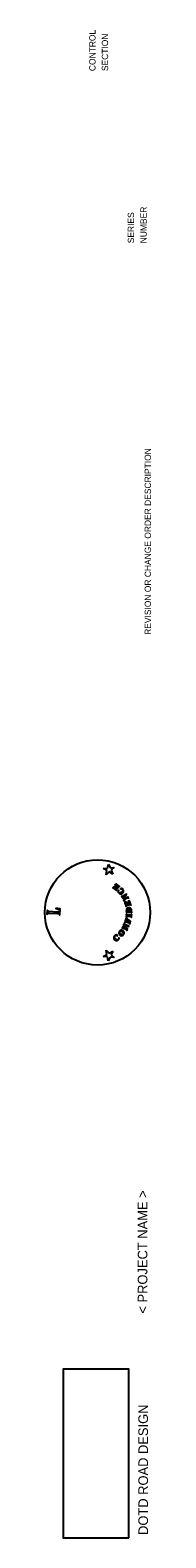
# Model space of a CAD drawing. Extents: x -31.4 to 41.1, y -13.7 to 22.3.
# Drawn here: x 39.92 to 41.13, y 0.56 to 17.76 of the extents above; entities that cross this region are included whole.
import ezdxf

# ---------------------------------------------------------------- set-up
doc = ezdxf.new("R2010")
doc.units = 0
doc.layers.add('Seal', color=7, linetype='Continuous')
doc.layers.add('Sheet Border', color=7, linetype='Continuous')

msp = doc.modelspace()

# ---------------------------------------------------------------- linework, layer by layer
at = {"layer": 'Seal'}
msp.add_lwpolyline([(40.878, 0.558), (40.878, 2.481), (40.128, 2.481), (40.128, 0.558)], close=True, dxfattribs=at)
at = {"layer": 'Sheet Border'}
for p, q in [((40.587, 8.192), (40.635, 8.198)), ((40.629, 8.169), (40.587, 8.192)), ((40.619, 8.122), (40.629, 8.169)), ((40.654, 8.154), (40.619, 8.122)), ((40.635, 8.198), (40.645, 8.244)), ((40.645, 8.244), (40.664, 8.2)), ((40.695, 8.13), (40.654, 8.154)), ((40.664, 8.2), (40.712, 8.206)), ((40.712, 8.206), (40.676, 8.174)), ((40.676, 8.174), (40.695, 8.13)), ((40.629, 7.214), (40.62, 7.261)), ((40.62, 7.261), (40.654, 7.229)), ((40.654, 7.229), (40.696, 7.252)), ((40.696, 7.252), (40.676, 7.209)), ((40.587, 7.191), (40.629, 7.214)), ((40.635, 7.185), (40.587, 7.191)), ((40.644, 7.139), (40.635, 7.185)), ((40.664, 7.183), (40.644, 7.139)), ((40.711, 7.177), (40.664, 7.183)), ((40.676, 7.209), (40.711, 7.177))]:
    msp.add_line(p, q, dxfattribs=at)
for points in [[(40.721, 7.958), (40.715, 7.963), (40.708, 7.969), (40.706, 7.973), (40.706, 7.976), (40.706, 7.98), (40.708, 7.985), (40.707, 7.986), (40.697, 7.974), (40.737, 7.942), (40.737, 7.943), (40.736, 7.945), (40.734, 7.947), (40.733, 7.949), (40.733, 7.951), (40.736, 7.955), (40.761, 7.986), (40.764, 7.99), (40.767, 7.991), (40.771, 7.989), (40.773, 7.987), (40.773, 7.988), (40.733, 8.02), (40.72, 8.007), (40.721, 8.007), (40.727, 8.01), (40.734, 8.011), (40.741, 8.01), (40.747, 8.006), (40.75, 8.004), (40.753, 8.001), (40.753, 7.998), (40.749, 7.993), (40.739, 7.98), (40.736, 7.983), (40.734, 7.985), (40.733, 7.988), (40.733, 7.991), (40.734, 7.995), (40.736, 7.999), (40.735, 8), (40.717, 7.977), (40.718, 7.976), (40.723, 7.98), (40.727, 7.982), (40.731, 7.982), (40.736, 7.979), (40.737, 7.978)], [(40.748, 7.931), (40.749, 7.93), (40.752, 7.931), (40.754, 7.93), (40.756, 7.925), (40.76, 7.919), (40.764, 7.914), (40.77, 7.909), (40.778, 7.906), (40.786, 7.905), (40.795, 7.906), (40.802, 7.909), (40.809, 7.914), (40.814, 7.92), (40.817, 7.927), (40.818, 7.935), (40.817, 7.942), (40.814, 7.95), (40.808, 7.957), (40.803, 7.961), (40.798, 7.964), (40.793, 7.966), (40.786, 7.967), (40.783, 7.963), (40.79, 7.963), (40.795, 7.962), (40.8, 7.96), (40.804, 7.957), (40.808, 7.952), (40.809, 7.947), (40.809, 7.942), (40.806, 7.936), (40.802, 7.929), (40.797, 7.924), (40.79, 7.918), (40.784, 7.915), (40.778, 7.913), (40.773, 7.913), (40.768, 7.915), (40.763, 7.918), (40.76, 7.923), (40.759, 7.93), (40.76, 7.937), (40.764, 7.944), (40.763, 7.945)], [(40.045, 7.74), (40.045, 7.737), (40.06, 7.733), (40.071, 7.73), (40.078, 7.726), (40.083, 7.722), (40.086, 7.718), (40.087, 7.712), (40.086, 7.706), (40.085, 7.699), (40.08, 7.696), (40.065, 7.697), (39.969, 7.702), (39.956, 7.703), (39.951, 7.706), (39.949, 7.711), (39.949, 7.714), (39.946, 7.714), (39.943, 7.674), (39.947, 7.674), (39.947, 7.676), (39.949, 7.681), (39.954, 7.684), (39.969, 7.684), (40.066, 7.679), (40.08, 7.677), (40.085, 7.674), (40.087, 7.669), (40.087, 7.666), (40.09, 7.666), (40.094, 7.734)], [(40.815, 7.843), (40.826, 7.826), (40.827, 7.827), (40.825, 7.83), (40.826, 7.835), (40.827, 7.836), (40.863, 7.858), (40.867, 7.86), (40.87, 7.86), (40.873, 7.858), (40.875, 7.855), (40.876, 7.856), (40.866, 7.872), (40.865, 7.872), (40.866, 7.871), (40.867, 7.868), (40.867, 7.865), (40.866, 7.863), (40.862, 7.86), (40.828, 7.84), (40.851, 7.901), (40.85, 7.902), (40.808, 7.877), (40.803, 7.874), (40.799, 7.875), (40.796, 7.879), (40.794, 7.878), (40.804, 7.861), (40.805, 7.862), (40.804, 7.866), (40.804, 7.869), (40.806, 7.872), (40.81, 7.874), (40.832, 7.888)], [(40.842, 7.781), (40.84, 7.788), (40.838, 7.797), (40.838, 7.801), (40.839, 7.805), (40.842, 7.808), (40.847, 7.811), (40.846, 7.812), (40.831, 7.807), (40.846, 7.759), (40.847, 7.76), (40.846, 7.762), (40.846, 7.764), (40.846, 7.766), (40.848, 7.769), (40.853, 7.77), (40.89, 7.782), (40.896, 7.783), (40.898, 7.782), (40.9, 7.778), (40.901, 7.776), (40.902, 7.776), (40.887, 7.825), (40.869, 7.822), (40.869, 7.821), (40.876, 7.82), (40.883, 7.818), (40.887, 7.813), (40.891, 7.806), (40.892, 7.802), (40.892, 7.798), (40.891, 7.796), (40.885, 7.794), (40.869, 7.789), (40.868, 7.793), (40.868, 7.796), (40.869, 7.799), (40.871, 7.801), (40.874, 7.804), (40.878, 7.806), (40.877, 7.807), (40.849, 7.799), (40.849, 7.797), (40.855, 7.798), (40.86, 7.797), (40.864, 7.794), (40.866, 7.79), (40.866, 7.788)], [(40.911, 7.689), (40.909, 7.715), (40.908, 7.723), (40.907, 7.728), (40.905, 7.733), (40.902, 7.736), (40.899, 7.74), (40.895, 7.742), (40.89, 7.744), (40.885, 7.746), (40.879, 7.746), (40.87, 7.744), (40.863, 7.741), (40.86, 7.738), (40.857, 7.736), (40.855, 7.732), (40.853, 7.729), (40.851, 7.721), (40.851, 7.712), (40.852, 7.686), (40.853, 7.686), (40.853, 7.688), (40.854, 7.692), (40.856, 7.694), (40.861, 7.695), (40.901, 7.697), (40.906, 7.697), (40.908, 7.695), (40.909, 7.691), (40.91, 7.689)], [(40.841, 7.6), (40.842, 7.604), (40.846, 7.614), (40.849, 7.617), (40.852, 7.619), (40.856, 7.62), (40.862, 7.62), (40.862, 7.621), (40.847, 7.626), (40.832, 7.579), (40.833, 7.579), (40.834, 7.581), (40.836, 7.584), (40.838, 7.586), (40.844, 7.584), (40.881, 7.572), (40.886, 7.57), (40.888, 7.568), (40.887, 7.564), (40.887, 7.562), (40.888, 7.561), (40.897, 7.591), (40.896, 7.591), (40.895, 7.589), (40.893, 7.585), (40.891, 7.584), (40.885, 7.585), (40.868, 7.591), (40.868, 7.593), (40.87, 7.597), (40.873, 7.6), (40.878, 7.601), (40.885, 7.601), (40.885, 7.602), (40.857, 7.611), (40.857, 7.61), (40.861, 7.608), (40.864, 7.605), (40.866, 7.603), (40.867, 7.6), (40.867, 7.597), (40.866, 7.594), (40.865, 7.592)], [(40.908, 7.668), (40.908, 7.666), (40.907, 7.662), (40.905, 7.66), (40.899, 7.66), (40.86, 7.662), (40.854, 7.663), (40.852, 7.665), (40.852, 7.67), (40.852, 7.672), (40.851, 7.672), (40.849, 7.641), (40.85, 7.641), (40.85, 7.643), (40.851, 7.647), (40.853, 7.649), (40.859, 7.649), (40.898, 7.646), (40.904, 7.646), (40.906, 7.644), (40.906, 7.639), (40.906, 7.637), (40.907, 7.637), (40.909, 7.668)], [(40.853, 7.708), (40.853, 7.714), (40.854, 7.718), (40.857, 7.722), (40.861, 7.725), (40.869, 7.728), (40.88, 7.73), (40.886, 7.73), (40.892, 7.729), (40.897, 7.728), (40.901, 7.726), (40.904, 7.724), (40.905, 7.721), (40.906, 7.719), (40.907, 7.715), (40.906, 7.712), (40.905, 7.711), (40.901, 7.71)], [(40.737, 7.442), (40.736, 7.442), (40.736, 7.439), (40.735, 7.436), (40.73, 7.434), (40.724, 7.432), (40.718, 7.428), (40.713, 7.422), (40.708, 7.415), (40.706, 7.407), (40.706, 7.399), (40.708, 7.391), (40.712, 7.384), (40.718, 7.378), (40.725, 7.374), (40.732, 7.372), (40.74, 7.372), (40.748, 7.375), (40.755, 7.379), (40.76, 7.384), (40.764, 7.388), (40.766, 7.394), (40.768, 7.4), (40.765, 7.404), (40.764, 7.397), (40.763, 7.391), (40.76, 7.387), (40.756, 7.383), (40.751, 7.38), (40.746, 7.379), (40.74, 7.381), (40.735, 7.384), (40.729, 7.389), (40.724, 7.395), (40.719, 7.401), (40.717, 7.408), (40.716, 7.414), (40.716, 7.419), (40.719, 7.424), (40.722, 7.428), (40.728, 7.431), (40.734, 7.432), (40.741, 7.43), (40.748, 7.425), (40.749, 7.426)], [(40.771, 7.477), (40.767, 7.472), (40.765, 7.467), (40.764, 7.461), (40.764, 7.455), (40.765, 7.449), (40.768, 7.444), (40.771, 7.439), (40.776, 7.435), (40.78, 7.431), (40.785, 7.429), (40.79, 7.428), (40.796, 7.427), (40.802, 7.428), (40.808, 7.43), (40.814, 7.434), (40.819, 7.439), (40.823, 7.446), (40.825, 7.452), (40.826, 7.458), (40.825, 7.465), (40.823, 7.47), (40.821, 7.475), (40.818, 7.479), (40.814, 7.483), (40.808, 7.486), (40.803, 7.488), (40.797, 7.489), (40.791, 7.489), (40.785, 7.488), (40.78, 7.486), (40.775, 7.482)], [(40.773, 7.476), (40.776, 7.479), (40.779, 7.48), (40.784, 7.48), (40.789, 7.479), (40.796, 7.475), (40.805, 7.469), (40.811, 7.463), (40.816, 7.458), (40.819, 7.452), (40.82, 7.448), (40.819, 7.444), (40.817, 7.441), (40.815, 7.439), (40.813, 7.437), (40.81, 7.436), (40.807, 7.436), (40.802, 7.437), (40.797, 7.439), (40.792, 7.442), (40.786, 7.447), (40.777, 7.454), (40.772, 7.462), (40.771, 7.466), (40.77, 7.469), (40.771, 7.473)], [(40.81, 7.53), (40.802, 7.512), (40.803, 7.512), (40.806, 7.515), (40.81, 7.517), (40.811, 7.517), (40.85, 7.499), (40.853, 7.497), (40.855, 7.495), (40.855, 7.492), (40.854, 7.488), (40.855, 7.487), (40.863, 7.505), (40.862, 7.506), (40.862, 7.504), (40.86, 7.502), (40.858, 7.501), (40.855, 7.5), (40.851, 7.501), (40.815, 7.518), (40.878, 7.534), (40.878, 7.535), (40.834, 7.555), (40.829, 7.558), (40.827, 7.561), (40.829, 7.567), (40.827, 7.567), (40.819, 7.55), (40.82, 7.549), (40.823, 7.553), (40.826, 7.555), (40.829, 7.554), (40.833, 7.553), (40.857, 7.542)]]:
    msp.add_lwpolyline(points, close=True, dxfattribs=at)
msp.add_circle((40.521, 7.692), 0.6, dxfattribs=at)

# ---------------------------------------------------------------- texts
for s, height, p in [('CONTROL', 0.072, (40.498, 17.29)), ('SECTION', 0.072, (40.642, 17.29)), ('SERIES', 0.072, (40.938, 15.326)), ('NUMBER', 0.072, (41.082, 15.326)), ('REVISION OR CHANGE ORDER DESCRIPTION', 0.072, (41.131, 10.859)), ('               < PROJECT NAME >               ', 0.11, (41.09, 2.503)), (' DOTD ROAD DESIGN', 0.11, (41.097, 0.55))]:
    msp.add_text(s, height=height, rotation=90, dxfattribs=at).set_placement(p)

doc.saveas('drawing.dxf')
